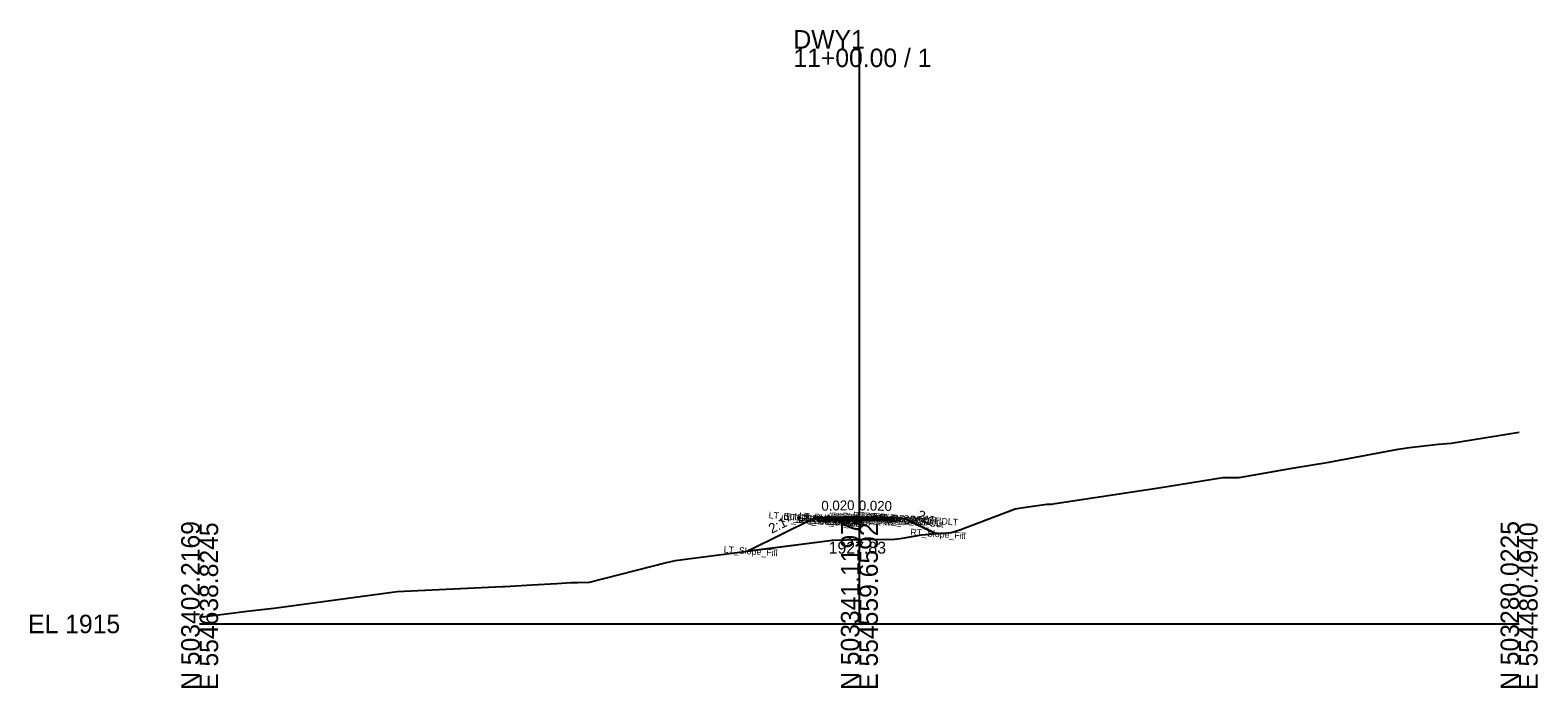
# Model space of a CAD drawing. Extents: x -26 to 203, y -10 to 1558.
# Drawn here: x -25.7 to 202.8, y 990.3 to 1090.1 of the extents above; entities that cross this region are included whole.
import ezdxf

# ---------------------------------------------------------------- set-up
doc = ezdxf.new("R2010")
doc.units = 0
for name, color, linetype in [('Default', 7, 'Continuous'), ('Exist Cross Section Cell', 7, 'Continuous'), ('Exist XS Center Line Elevation Label', 7, 'Continuous'), ('Exist XS Ground Line', 7, 'Continuous'), ('Prop CMT Pvmt Course 1', 7, 'Continuous'), ('Prop CMT Pvmt Course 2', 7, 'Continuous'), ('Prop CMT Pvmt Surface', 7, 'Continuous'), ('Prop CMT Shld Paved Course 1', 7, 'Continuous'), ('Prop CMT Shld Paved Course 2', 7, 'Continuous'), ('Prop CMT Slope Grass', 7, 'Continuous'), ('Prop CMT Subgrade Earthwork', 7, 'Continuous'), ('Prop XS Earthwork Shape', 7, 'Continuous'), ('Prop XS SE Text', 7, 'Continuous'), ('Prop XS Side Slope Text', 7, 'Continuous'), ('Typical Text Asphalt at Bridge Approach CELL', 7, 'Continuous')]:
    doc.layers.add(name, color=color, linetype=linetype)

msp = doc.modelspace()

# ---------------------------------------------------------------- linework, layer by layer
at = {"layer": 'Exist Cross Section Cell'}
for p, q in [((100, 1000), (100, 1087.27)), ((0, 1000), (100, 1000)), ((100, 1000), (200, 1000))]:
    msp.add_line(p, q, dxfattribs=at)
at = {"layer": 'Exist XS Ground Line'}
for p, q in [((189.71, 1027.4), (200, 1029.09)), ((171.17, 1024.56), (181.69, 1026.52)), ((181.69, 1026.52), (183.37, 1026.78)), ((183.37, 1026.78), (187.8, 1027.28)), ((187.8, 1027.28), (189.71, 1027.4)), ((165.89, 1023.67), (171.17, 1024.56)), ((145.38, 1020.64), (155.07, 1022.24)), ((155.07, 1022.24), (157.59, 1022.24)), ((157.59, 1022.24), (165.89, 1023.67)), ((129.66, 1018.26), (145.38, 1020.64)), ((115.22, 1014.29), (123.6, 1017.48)), ((123.6, 1017.48), (124.51, 1017.61)), ((124.51, 1017.61), (128.39, 1018.16)), ((128.39, 1018.16), (129.13, 1018.17)), ((129.13, 1018.17), (129.66, 1018.26)), ((73.23, 1009.78), (95.93, 1012.71)), ((95.93, 1012.71), (100.13, 1012.83)), ((100.13, 1012.83), (105.34, 1012.88)), ((105.34, 1012.88), (106.23, 1012.95)), ((106.23, 1012.95), (108.86, 1013.43)), ((108.86, 1013.43), (109.44, 1013.54)), ((109.44, 1013.54), (113.9, 1013.87)), ((113.9, 1013.87), (115.22, 1014.29)), ((59.09, 1006.35), (70.78, 1009.33)), ((70.78, 1009.33), (72.13, 1009.63)), ((72.13, 1009.63), (73.23, 1009.78)), ((29.93, 1004.9), (45.92, 1005.67)), ((45.92, 1005.67), (46.26, 1005.68)), ((46.26, 1005.68), (50.34, 1005.94)), ((50.34, 1005.94), (54.13, 1006.12)), ((54.13, 1006.12), (56.32, 1006.29)), ((56.32, 1006.29), (57.3, 1006.29)), ((57.3, 1006.29), (59.09, 1006.35)), ((11.23, 1002.42), (29.93, 1004.9)), ((0, 1001.03), (3.63, 1001.49)), ((3.63, 1001.49), (7.59, 1001.97)), ((7.59, 1001.97), (11.23, 1002.42))]:
    msp.add_line(p, q, dxfattribs=at)
at = {"layer": 'Prop CMT Pvmt Course 1'}
for points in [[(100, 1016.23), (95, 1016.13)], [(95, 1016.13), (95, 1015.88)], [(95, 1015.88), (100, 1015.98)], [(100, 1015.98), (100, 1016.23)], [(100, 1016.23), (105, 1016.13)], [(100, 1015.98), (100, 1016.23)], [(105, 1015.88), (100, 1015.98)], [(105, 1016.13), (105, 1015.88)]]:
    msp.add_lwpolyline(points, dxfattribs=at)
msp.add_lwpolyline([(100, 1015.98), (100, 1016.1), (100, 1016.1), (100, 1015.98)], close=True, dxfattribs=at)
msp.add_lwpolyline([(100, 1015.98), (100, 1016.1), (100, 1016.1), (100, 1015.98)], close=True, dxfattribs=at)
at = {"layer": 'Prop CMT Pvmt Course 2'}
for points in [[(100, 1015.98), (95, 1015.88)], [(95, 1015.88), (95, 1015.63)], [(95, 1015.63), (100, 1015.73)], [(100, 1015.73), (100, 1015.98)], [(100, 1015.73), (100, 1015.98)], [(100, 1015.98), (105, 1015.88)], [(105, 1015.63), (100, 1015.73)], [(105, 1015.88), (105, 1015.63)]]:
    msp.add_lwpolyline(points, dxfattribs=at)
at = {"layer": 'Prop CMT Pvmt Surface'}
for points in [[(100, 1016.23), (95, 1016.13)], [(100, 1016.23), (105, 1016.13)]]:
    msp.add_lwpolyline(points, dxfattribs=at)
at = {"layer": 'Prop CMT Shld Paved Course 1'}
for points in [[(95, 1016.13), (94.49, 1015.62)], [(94.74, 1015.87), (95, 1015.88)], [(95, 1015.88), (95, 1016.13)], [(105, 1016.13), (105.51, 1015.62)], [(105, 1015.88), (105, 1016.13)], [(105.26, 1015.87), (105, 1015.88)]]:
    msp.add_lwpolyline(points, dxfattribs=at)
at = {"layer": 'Prop CMT Shld Paved Course 2'}
for points in [[(95, 1015.63), (95, 1015.88)], [(105, 1015.63), (105, 1015.88)]]:
    msp.add_lwpolyline(points, dxfattribs=at)
at = {"layer": 'Prop CMT Slope Grass'}
for points in [[(95, 1016.13), (93, 1015.97), (83.2, 1011.07)], [(105, 1016.13), (107, 1015.97), (111.54, 1013.7)]]:
    msp.add_lwpolyline(points, dxfattribs=at)
at = {"layer": 'Prop CMT Subgrade Earthwork'}
for p, q in [((94.49, 1015.62), (94.06, 1016.05)), ((95, 1015.63), (94.49, 1015.62)), ((105, 1015.63), (105.51, 1015.62)), ((105.51, 1015.62), (105.94, 1016.05))]:
    msp.add_line(p, q, dxfattribs=at)
for points in [[(100, 1015.73), (95, 1015.63)], [(100, 1015.73), (105, 1015.63)]]:
    msp.add_lwpolyline(points, dxfattribs=at)
at = {"layer": 'Prop XS Earthwork Shape'}
msp.add_lwpolyline([(100, 1015.73), (95, 1015.63), (93.99, 1015.61), (93.58, 1016.01), (93, 1015.97), (83.2, 1011.07), (95.93, 1012.71), (100.13, 1012.83), (105.34, 1012.88), (106.23, 1012.95), (108.86, 1013.43), (109.44, 1013.54), (111.54, 1013.7), (107, 1015.97), (106.42, 1016.01), (106.01, 1015.61), (105, 1015.63)], close=True, dxfattribs=at)

# ---------------------------------------------------------------- texts
at = {"layer": 'Default'}
msp.add_text('-', height=0.0001, dxfattribs=at).set_placement((0, 1000))
at = {"layer": 'Exist Cross Section Cell'}
for s, p in [('DWY1', (90, 1087.27)), ('11+00.00 / 1', (90, 1084.47)), ('EL 1915', (-26, 998.6))]:
    msp.add_text(s, height=2.8, dxfattribs=at).set_placement(p)
for s, p in [('N 503402.2169', (0, 990)), ('E 554638.8245', (2.8, 990)), ('N 503341.1197', (100, 990)), ('E 554559.6592', (102.8, 990)), ('N 503280.0225', (200, 990)), ('E 554480.4940', (202.8, 990))]:
    msp.add_text(s, height=2.8, rotation=90, dxfattribs=at).set_placement(p)
at = {"layer": 'Exist XS Center Line Elevation Label'}
msp.add_text('1927.83', height=1.8, dxfattribs=at).set_placement((95.34, 1010.67))
at = {"layer": 'Prop XS SE Text'}
for rotation, p in [(1.1458, (94.25, 1017.17)), (358.8542, (99.9, 1017.23))]:
    msp.add_text('0.020', height=1.5, rotation=rotation, dxfattribs=at).set_placement(p)
at = {"layer": 'Prop XS Side Slope Text'}
for rotation, p in [(333.4349, (108.54, 1016.03)), (26.5651, (86.7, 1013.66))]:
    msp.add_text('2:1', height=1.5, rotation=rotation, dxfattribs=at).set_placement(p)
at = {"layer": 'Typical Text Asphalt at Bridge Approach CELL'}
for s, p in [('LT_Sub_Trench_Out_DLT', (86.22, 1016.03)), ('RT_Sub_Trench_Out_DLT', (98.99, 1016.03)), ('LT_Sub_Trench_Out', (88.08, 1015.52)), ('LT_GS_OS_CTL', (88.44, 1015.79)), ('LT_PS2_Shelf_Out', (88.88, 1015.74)), ('LT_PS2_OEOP', (90.51, 1015.67)), ('LT_PV2_OEOT', (90.72, 1015.68)), ('LT_Sub_OEOT', (90.74, 1015.42)), ('LT_PV1_OEOT', (90.84, 1015.92)), ('RT_PV2_OEEOP', (95.31, 1015.8)), ('RT_Sub_OEEOP', (95.33, 1015.55)), ('LT_PV2_OEEOP', (95.37, 1015.8)), ('LT_Sub_OEEOP', (95.39, 1015.55)), ('RT_PV1_OEEOP', (95.43, 1015.92)), ('LT_PV1_OEEOP', (95.49, 1015.92)), ('RT_PV2_IEEOP', (95.69, 1015.78)), ('LT_PV2_IEEOP', (95.75, 1015.77)), ('RT_PV1_IEEOP', (95.81, 1015.89)), ('LT_PV1_IEEOP', (95.87, 1015.89)), ('PV2_PGL', (97.32, 1015.66)), ('PV1_PGL', (97.44, 1015.91)), ('RT_Sub_Trench_Out', (100.04, 1015.52)), ('RT_PS2_Shelf_Out', (100.33, 1015.74)), ('RT_PV2_OEOT', (100.66, 1015.68)), ('RT_Sub_OEOT', (100.69, 1015.43)), ('RT_PV1_OEOT', (100.78, 1015.92)), ('RT_PS2_OEOP', (100.96, 1015.67)), ('RT_GS_OS_CTL', (102.38, 1015.79)), ('RT_Slope_Fill', (107.7, 1013.46)), ('LT_Slope_Fill', (79.41, 1010.83))]:
    msp.add_text(s, height=1, rotation=356, dxfattribs=at).set_placement(p)

doc.saveas('drawing.dxf')
